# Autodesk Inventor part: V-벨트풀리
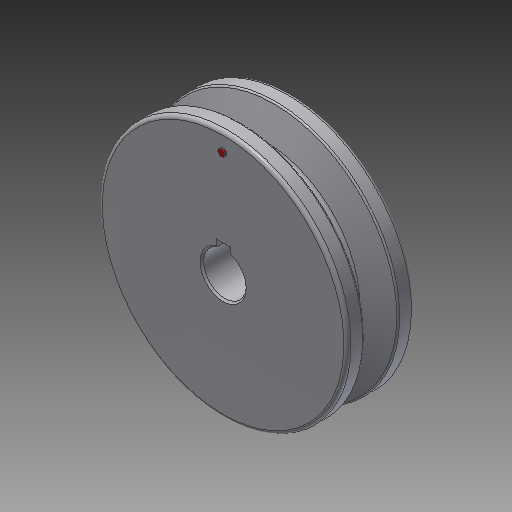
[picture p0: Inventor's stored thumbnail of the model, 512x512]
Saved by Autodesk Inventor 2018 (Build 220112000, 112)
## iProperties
Created: 2016-08
Part Number: V-벨트풀리
Material: 알루미늄 6061
Document SubType Name: Modeling
Designer: mduedu
Density: 2.71 g/cm^3
Appearance: 알루미늄 - 평지
Author: mduedu
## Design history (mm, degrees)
sketch "스케치1"
  geometry: L1 (0, 9.5)-(0, -9.5); L2 (0, 9.5)-(35, 9.5); L3 (35, 9.5)-(35, 4.825); L4 (35, 4.825)-(26, 2.074); L5 (26, 2.074)-(26, 0); L6 (0, 0)-(26, 0); L7 (0, -9.5)-(35, -9.5); L8 (35, -9.5)-(35, -4.825); L9 (35, -4.825)-(26, -2.074); L10 (26, -2.074)-(26, 0); L11 (32.3, 9.5)-(32.3, -9.5); 3 further points
  constraints: 22 end point, 6 point on line, 4 perpendicular, 3 symmetric about line, 1 coincident, 1 horizontal alignment, 1 midpoint, 1 parallel, 1 vertical
  dimensions: "d0" = 19 distance of L1.start L1.end; "d2" = 70 diameter of L8 L1; "d4" = 6.3 distance between parallel lines of L10 L11; "d5" = 2.7 distance between parallel lines of L11 L8; "d6" = 8 distance of point (32.3, -4) point (32.3, 4); "d7" = 34 deg angle of L9 L4
revolve "회전1" sketch "스케치1" stored, may be unused: angle "d8" = 90 deg
sketch "스케치2"
  geometry: L1 (-2, 0)-(2, 0); L2 (2, 0)-(2, 7.8); L3 (2, 7.8)-(-2, 7.8); L4 (-2, 7.8)-(-2, 0); C1 r 6 at (0, 0); 2 further points
  constraints: 8 end point, 2 coincident, 2 parallel, 1 centre point, 1 horizontal, 1 midpoint, 1 perpendicular
  dimensions: "d9" = 12 diameter of C1; "d11" = 4 distance of L2.end L3.end; "d12" = 7.8 distance of L1.end L2.end
extrude "돌출1" cut sketch "스케치2" extent not by distance; stored distance "d13" = 10; taper "d14" = 0 deg
sketch "스케치4"
  geometry: C1 r 22 at (0, 0); C2 r 12 at (0, 0); 1 further point
  constraints: 2 centre point, 2 coincident
  dimensions: "d32" = 44 diameter of C1; "d34" = 24 diameter of C2
extrude "돌출2" cut sketch "스케치4" distance "d35" = 12; taper "d36" = 0 deg
fillet "모깎기1" dims "d20" = 0.5, "d21" = 1, "d37" = 1
fillet "모깎기6" dims "d38" = 3
chamfer "모따기1" distance "d26" = 0.5; stored, may be unused: second distance "d27" = 2, angle "d28" = 45 deg
sketch "스케치5" dims "d39" = 60
  geometry: C1 r 1 at (0, 30); 2 further points
  constraints: 2 vertical alignment, 1 centre point, 1 coincident, 2 other
  dimensions: "d40" = 2 diameter of C1
extrude "돌출3" join sketch "스케치5" distance "d41" = 0.5; taper "d42" = 0 deg
node "솔리드1"
